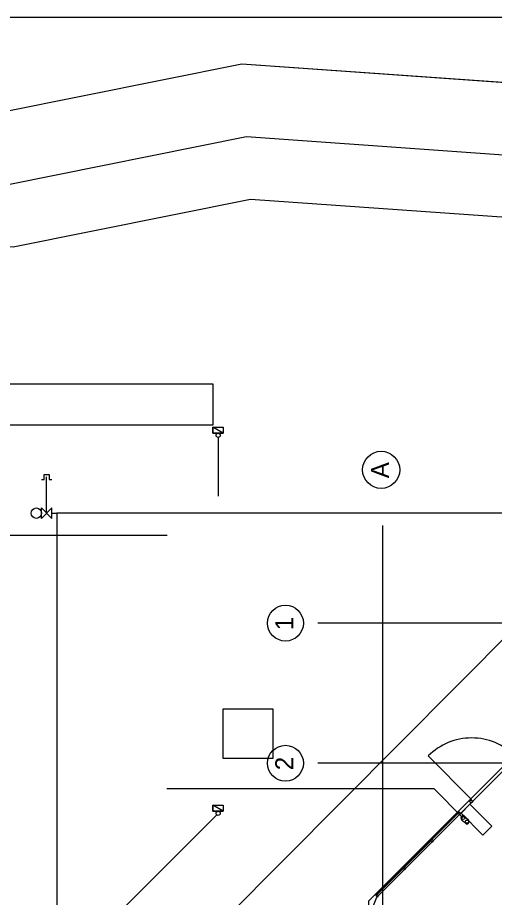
# Model space of a CAD drawing. Extents: x -264031 to -263588, y -1242281 to -1242059.
# Drawn here: x -263926.05 to -263902.97, y -1242101.22 to -1242058.68 of the extents above; entities that cross this region are included whole.
import ezdxf

# ---------------------------------------------------------------- set-up
doc = ezdxf.new("R2010")
doc.units = 0
for name, color, linetype in [('HESCON_OSI_STAVBY_KFA', 7, 'Continuous'), ('KFA_2D_SITUACIA_DSP', 7, 'Continuous'), ('KFA_JESTV_IS_DSP_-_KANAL_SPLASK', 7, 'Continuous'), ('RAM_NA_TLAC_3xA4_1-750', 7, 'Continuous')]:
    doc.layers.add(name, color=color, linetype=linetype)

msp = doc.modelspace()

# ---------------------------------------------------------------- linework, layer by layer
at = {"layer": 'HESCON_OSI_STAVBY_KFA'}
for p, q in [((-263908.393, -1242083.237), (-263908.393, -1242083.237)), ((-263908.393, -1242083.237), (-263908.393, -1242246.707)), ((-263792.653, -1242087.957), (-263911.523, -1242087.957)), ((-263792.653, -1242094.732), (-263911.523, -1242094.732))]:
    msp.add_line(p, q, dxfattribs=at)
for centre, radius in [((-263908.453, -1242080.545), 0.899), ((-263913.085, -1242087.958), 0.867), ((-263913.085, -1242094.733), 0.867)]:
    msp.add_circle(centre, radius, dxfattribs=at)
at = {"layer": 'KFA_2D_SITUACIA_DSP'}
for p, q in [((-263915.197, -1242060.921), (-263926.771, -1242063.254)), ((-263895.455, -1242062.322), (-263915.197, -1242060.921)), ((-263926.968, -1242076.382), (-263921.968, -1242076.382)), ((-263921.968, -1242076.382), (-263916.593, -1242076.382)), ((-263916.593, -1242076.382), (-263916.593, -1242078.382)), ((-263921.968, -1242078.382), (-263926.968, -1242078.382)), ((-263916.593, -1242078.382), (-263921.968, -1242078.382)), ((-263916.593, -1242078.777), (-263916.593, -1242078.487)), ((-263916.593, -1242078.487), (-263916.093, -1242078.487)), ((-263916.093, -1242078.777), (-263916.593, -1242078.487)), ((-263916.093, -1242078.777), (-263916.593, -1242078.487)), ((-263916.593, -1242078.487), (-263916.593, -1242078.777)), ((-263916.093, -1242078.487), (-263916.093, -1242078.777)), ((-263916.093, -1242078.777), (-263916.593, -1242078.777)), ((-263916.593, -1242078.777), (-263916.093, -1242078.777)), ((-263916.343, -1242078.977), (-263916.343, -1242081.82)), ((-263924.768, -1242081.015), (-263924.768, -1242080.765)), ((-263924.768, -1242080.765), (-263924.518, -1242080.765)), ((-263924.518, -1242080.765), (-263924.518, -1242081.015)), ((-263924.893, -1242081.015), (-263924.768, -1242081.015)), ((-263924.643, -1242082.64), (-263924.643, -1242080.89)), ((-263924.518, -1242081.015), (-263924.393, -1242081.015)), ((-263924.393, -1242082.39), (-263924.893, -1242082.89)), ((-263924.893, -1242082.89), (-263924.893, -1242082.39)), ((-263924.893, -1242082.39), (-263924.393, -1242082.89)), ((-263924.393, -1242082.89), (-263924.393, -1242082.39)), ((-263924.393, -1242082.64), (-263924.143, -1242082.64)), ((-263788.143, -1242082.64), (-263924.143, -1242082.64)), ((-263924.143, -1242082.64), (-263924.143, -1242185.14)), ((-263951.618, -1242083.697), (-263918.806, -1242083.697)), ((-263908.663, -1242101.215), (-263895.135, -1242087.687)), ((-263916.093, -1242092.107), (-263913.693, -1242092.107)), ((-263916.093, -1242094.507), (-263916.093, -1242092.107)), ((-263913.693, -1242092.107), (-263913.693, -1242094.507)), ((-263904.074, -1242096.484), (-263906.177, -1242094.38)), ((-263913.693, -1242094.507), (-263916.093, -1242094.507)), ((-263905.894, -1242095.971), (-263918.832, -1242095.971)), ((-263904.533, -1242097.332), (-263905.894, -1242095.971)), ((-263904.176, -1242096.586), (-263904.091, -1242096.501)), ((-263904.091, -1242096.501), (-263904.074, -1242096.484)), ((-263904.091, -1242096.501), (-263904.006, -1242096.586)), ((-263916.593, -1242097.052), (-263916.593, -1242096.762)), ((-263916.593, -1242096.762), (-263916.093, -1242096.762)), ((-263916.093, -1242097.052), (-263916.593, -1242096.762)), ((-263916.093, -1242097.052), (-263916.593, -1242096.762)), ((-263916.593, -1242096.762), (-263916.593, -1242097.052)), ((-263916.093, -1242096.762), (-263916.093, -1242097.052)), ((-263904.586, -1242097.143), (-263904.162, -1242096.719)), ((-263904.091, -1242096.671), (-263904.176, -1242096.586)), ((-263904.162, -1242096.719), (-263903.101, -1242097.779)), ((-263904.006, -1242096.586), (-263904.091, -1242096.671)), ((-263916.414, -1242097.223), (-263926.239, -1242107.049)), ((-263916.093, -1242097.052), (-263916.593, -1242097.052)), ((-263916.593, -1242097.052), (-263916.093, -1242097.052)), ((-263904.711, -1242097.1), (-263906.019, -1242098.408)), ((-263906.001, -1242098.426), (-263904.693, -1242097.118)), ((-263904.698, -1242097.123), (-263904.726, -1242097.151)), ((-263904.726, -1242097.151), (-263904.656, -1242097.222)), ((-263904.693, -1242097.118), (-263904.711, -1242097.1)), ((-263904.67, -1242097.095), (-263904.698, -1242097.123)), ((-263904.599, -1242097.165), (-263904.67, -1242097.095)), ((-263904.656, -1242097.222), (-263904.599, -1242097.165)), ((-263903.526, -1242098.203), (-263904.586, -1242097.143)), ((-263904.319, -1242097.381), (-263904.397, -1242097.303)), ((-263904.319, -1242097.401), (-263904.319, -1242097.381)), ((-263904.231, -1242097.489), (-263904.319, -1242097.401)), ((-263904.484, -1242097.547), (-263904.563, -1242097.468)), ((-263904.563, -1242097.468), (-263904.484, -1242097.547)), ((-263904.465, -1242097.547), (-263904.484, -1242097.547)), ((-263904.376, -1242097.635), (-263904.465, -1242097.547)), ((-263903.101, -1242097.779), (-263903.526, -1242098.203)), ((-263906.055, -1242098.444), (-263907.363, -1242099.752)), ((-263907.345, -1242099.77), (-263906.037, -1242098.462)), ((-263906.037, -1242098.462), (-263906.055, -1242098.444)), ((-263906.017, -1242098.442), (-263906.046, -1242098.47)), ((-263906.046, -1242098.47), (-263905.975, -1242098.541)), ((-263906.019, -1242098.408), (-263906.001, -1242098.426)), ((-263905.989, -1242098.414), (-263906.017, -1242098.442)), ((-263905.918, -1242098.485), (-263905.989, -1242098.414)), ((-263905.975, -1242098.541), (-263905.918, -1242098.485)), ((-263908.703, -1242101.092), (-263907.395, -1242099.784)), ((-263907.377, -1242099.802), (-263908.685, -1242101.11)), ((-263907.395, -1242099.784), (-263907.377, -1242099.802)), ((-263907.361, -1242099.786), (-263907.39, -1242099.814)), ((-263907.39, -1242099.814), (-263907.319, -1242099.885)), ((-263907.363, -1242099.752), (-263907.345, -1242099.77)), ((-263907.333, -1242099.758), (-263907.361, -1242099.786)), ((-263907.262, -1242099.828), (-263907.333, -1242099.758)), ((-263907.319, -1242099.885), (-263907.262, -1242099.828)), ((-263908.893, -1242101.769), (-263908.663, -1242101.215)), ((-263908.68, -1242101.105), (-263908.709, -1242101.134)), ((-263908.709, -1242101.134), (-263908.638, -1242101.204)), ((-263908.685, -1242101.11), (-263908.703, -1242101.092)), ((-263908.652, -1242101.077), (-263908.68, -1242101.105)), ((-263908.581, -1242101.148), (-263908.652, -1242101.077)), ((-263908.638, -1242101.204), (-263908.581, -1242101.148))]:
    msp.add_line(p, q, dxfattribs=at)
for points in [[(-263863.949, -1242065.106), (-263895.455, -1242062.322), (-263915.197, -1242060.921), (-263926.771, -1242063.254), (-263950.745, -1242062.149), (-263959.468, -1242059.534)], [(-263864.257, -1242068.593), (-263895.733, -1242065.811), (-263914.971, -1242064.445), (-263926.501, -1242066.77), (-263951.337, -1242065.625), (-263959.611, -1242063.145)], [(-263864.521, -1242071.581), (-263895.971, -1242068.802), (-263914.777, -1242067.467), (-263926.271, -1242069.784), (-263951.845, -1242068.605), (-263959.611, -1242066.277)], [(-263794.893, -1242227.382), (-263808.968, -1242241.457), (-263894.968, -1242241.457), (-263909.043, -1242227.382), (-263909.043, -1242196.333), (-263914.143, -1242196.333), (-263914.143, -1242132.433), (-263909.043, -1242132.433), (-263909.043, -1242101.382), (-263894.968, -1242087.307), (-263808.968, -1242087.307), (-263794.893, -1242101.382), (-263794.893, -1242227.382)]]:
    msp.add_lwpolyline(points, dxfattribs=at)
for centre, radius in [((-263916.343, -1242078.877), 0.1), ((-263925.143, -1242082.64), 0.25), ((-263916.343, -1242097.152), 0.1), ((-263904.48, -1242097.385), 0.075), ((-263904.303, -1242097.562), 0.075)]:
    msp.add_circle(centre, radius, dxfattribs=at)
for centre, radius, start, end in [((-263904.074, -1242096.484), 2.975, 44.9999, 134.9999), ((-263904.48, -1242097.385), 0.117, 45, 225), ((-263904.303, -1242097.562), 0.103, 225, 45)]:
    msp.add_arc(centre, radius, start, end, dxfattribs=at)
at = {"layer": 'KFA_JESTV_IS_DSP_-_KANAL_SPLASK'}
msp.add_line((-263897.853, -1242084.022), (-263922.202, -1242108.463), dxfattribs=at)
at = {"layer": 'RAM_NA_TLAC_3xA4_1-750'}
msp.add_lwpolyline([(-264030.986, -1242281.427), (-263873.486, -1242281.427), (-263730.986, -1242281.427), (-263588.486, -1242281.427), (-263588.486, -1242058.677), (-263730.986, -1242058.677), (-263873.486, -1242058.677), (-264030.986, -1242058.677)], close=True, dxfattribs=at)

# ---------------------------------------------------------------- texts
at = {"layer": 'HESCON_OSI_STAVBY_KFA'}
for s, p in [('A', (-263908.072, -1242080.952)), ('1', (-263912.704, -1242088.298)), ('2', (-263912.704, -1242095.073))]:
    msp.add_text(s, height=0.875, rotation=90, dxfattribs=at).set_placement(p)

doc.saveas('drawing.dxf')
